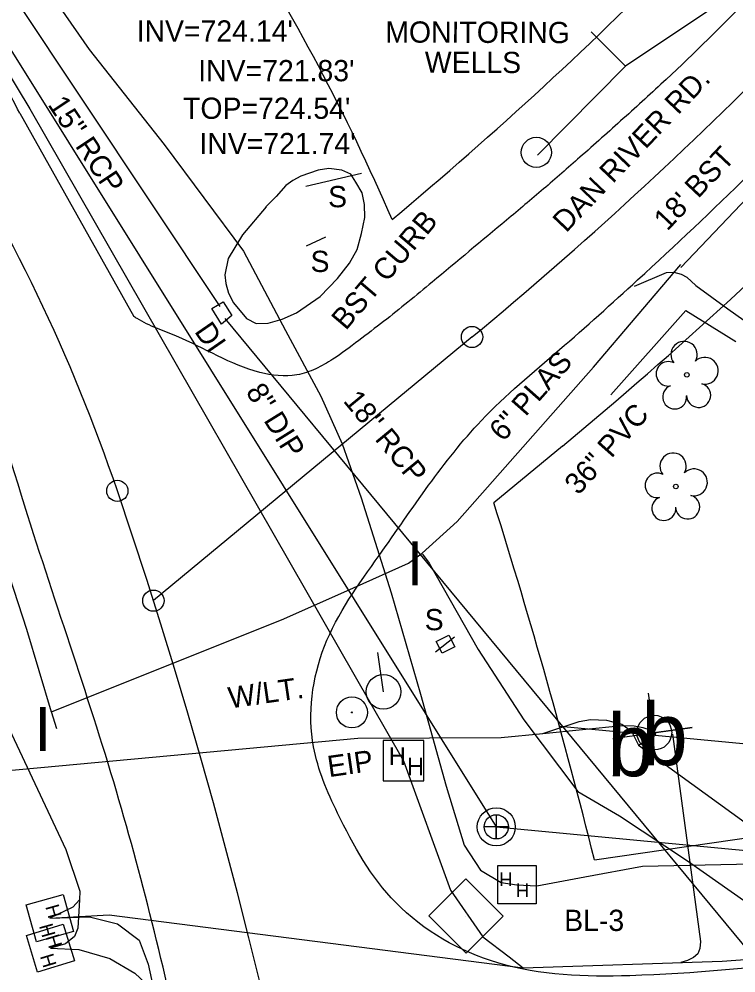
# Model space of a CAD drawing. Extents: x 1645945 to 2447332, y 713118 to 970361.
# Drawn here: x 1646260.5 to 1646361.8, y 969454.4 to 969589.2 of the extents above; entities that cross this region are included whole.
import ezdxf

# ---------------------------------------------------------------- set-up
doc = ezdxf.new("R2010")
doc.units = 0
for name, color, linetype in [('CTL Secondary Horizontal and Vertical CELL', 7, 'Continuous'), ('CTL Secondary Horizontal and Vertical Text', 7, 'Continuous'), ('Exist Horizontal Alignment', 7, 'Continuous'), ('Exist Horizontal Alignment Station Label', 7, 'Continuous'), ('Exist Other Culture Area Outline', 7, 'Continuous'), ('Exist Other Culture Area Outline Text', 7, 'Continuous'), ('Exist Other Culture Fence Line', 7, 'Continuous'), ('Exist Other Culture Fence Line Text', 7, 'Continuous'), ('Exist Other Culture Sign CELL', 7, 'Continuous'), ('Exist Other Culture Well CELL', 7, 'Continuous'), ('Exist Other Culture Well Leader', 7, 'Continuous'), ('Exist Other Culture Well Text', 7, 'Continuous'), ('Exist Property Iron Pin CELL', 7, 'Continuous'), ('Exist Property Iron Pin Text', 7, 'Continuous'), ('Exist Right of Way Easement Line', 7, 'Continuous'), ('Exist Right of Way Line', 7, 'Continuous'), ('Exist Roads Curbs', 7, 'Continuous'), ('Exist Roads Curbs Text', 7, 'Continuous'), ('Exist Roads EOP', 7, 'Continuous'), ('Exist Roads EOP Text', 7, 'Continuous'), ('Exist Roads Soil', 7, 'Continuous'), ('Exist Structure Minor Drop Inlet', 7, 'Continuous'), ('Exist Structure Minor Drop Inlet Text', 7, 'Continuous'), ('Exist Structure Minor Drop Inlet Top Elevation', 7, 'Continuous'), ('Exist Structure Minor Pipes RCP 15 Inch', 7, 'Continuous'), ('Exist Structure Minor Pipes RCP 15 Inch Invert', 7, 'Continuous'), ('Exist Structure Minor Pipes RCP 15 Inch Text', 7, 'Continuous'), ('Exist Structure Minor Pipes RCP 18 Inch', 7, 'Continuous'), ('Exist Structure Minor Pipes RCP 18 Inch Text', 7, 'Continuous'), ('Exist Utilities Power Joint Use Telephone CELL', 7, 'Continuous'), ('Exist Utilities Power Pole CELL', 7, 'Continuous'), ('Exist Utilities Power Pole Text', 7, 'Continuous'), ('Exist Utilities Sanitary Sewer Manhole CELL', 7, 'Continuous'), ('Exist Utilities Sanitary Sewer UG Line', 7, 'Continuous'), ('Exist Utilities Sanitary Sewer UG Line Text', 7, 'Continuous'), ('Exist Utilities Telephone Hand Hole CELL', 7, 'Continuous'), ('Exist Utilities Telephone Pedestal CELL', 7, 'Continuous'), ('Exist Utilities Telephone UG Cable SUE LOS C', 7, 'Continuous'), ('Exist Utilities Telephone UG Conduit SUE LOS B', 7, 'Continuous'), ('Exist Utilities Telephone UG FO SUE LOS C', 7, 'Continuous'), ('Exist Utilities Water UG Line SUE LOS B', 7, 'Continuous'), ('Exist Utilities Water UG Line SUE LOS B Text', 7, 'Continuous'), ('Exist Utilities Water UG Line SUE LOS C', 7, 'Continuous'), ('Exist Utilities Water Valve CELL', 7, 'Continuous'), ('Exist Vegetation Tree CELL', 7, 'Continuous')]:
    doc.layers.add(name, color=color, linetype=linetype)

msp = doc.modelspace()

# ---------------------------------------------------------------- linework, layer by layer
at = {"layer": 'CTL Secondary Horizontal and Vertical CELL'}
msp.add_line((1646323.61, 969462.44), (1646323.61, 969462.44), dxfattribs=at)
msp.add_lwpolyline([(1646318.4, 969462.45), (1646323.64, 969467.69), (1646328.89, 969462.44), (1646323.65, 969457.2)], close=True, dxfattribs=at)
at = {"layer": 'Exist Horizontal Alignment'}
msp.add_line((1646324.5, 969544.25), (1646279.5, 969507), dxfattribs=at)
for centre, radius, start, end in [((1645951.5, 969994.91), 585, 309.61403, 315.58305), ((1646037.69, 969442.13), 250, 18.755, 32.506), ((1645516.89, 969265.29), 800, 348.6692, 18.755)]:
    msp.add_arc(centre, radius, start, end, dxfattribs=at)
at = {"layer": 'Exist Horizontal Alignment Station Label'}
for centre in [(1646324.5, 969544.25), (1646274.41, 969522.51), (1646279.5, 969507)]:
    msp.add_circle(centre, 1.5, dxfattribs=at)
at = {"layer": 'Exist Other Culture Area Outline'}
msp.add_line((1646319.33, 969499.79), (1646322.04, 969501.87), dxfattribs=at)
msp.add_lwpolyline([(1646320.26, 969499.57), (1646319.42, 969501.22), (1646321.21, 969502.13), (1646322.05, 969500.47)], close=True, dxfattribs=at)
at = {"layer": 'Exist Other Culture Fence Line'}
msp.add_lwpolyline([(1646344.12, 969536.08), (1646354.69, 969547.97), (1646361.73, 969543.63)], dxfattribs=at)
at = {"layer": 'Exist Other Culture Sign CELL'}
for p, q in [((1646308.88, 969567.37), (1646301.02, 969565.53)), ((1646303.79, 969558.36), (1646301.06, 969557.1))]:
    msp.add_line(p, q, dxfattribs=at)
at = {"layer": 'Exist Other Culture Well CELL'}
msp.add_circle((1646333.58, 969570.33), 2.13, dxfattribs=at)
at = {"layer": 'Exist Other Culture Well Leader'}
msp.add_line((1646333.76, 969569.92), (1646346.18, 969582.49), dxfattribs=at)
msp.add_lwpolyline([(1646359.5, 969591.41), (1646346.18, 969582.49), (1646341.32, 969587.35)], dxfattribs=at)
at = {"layer": 'Exist Property Iron Pin CELL'}
for radius in [2.2, 0.0707]:
    msp.add_circle((1646307.54, 969491.21), radius, dxfattribs=at)
at = {"layer": 'Exist Right of Way Easement Line'}
msp.add_lwpolyline([(1646336.92, 969489.25), (1646418.86, 969481.48)], dxfattribs=at)
at = {"layer": 'Exist Right of Way Line'}
for p, q in [((1646341.77, 969470.4), (1647145.86, 969586)), ((1646337.25, 969528.84), (1646327.57, 969520.83))]:
    msp.add_line(p, q, dxfattribs=at)
for centre, radius, start, end in [((1646037.69, 969442.13), 300, 23.3127, 32.506), ((1645951.5, 969994.91), 565, 309.8047, 315.5831), ((1645951.5, 969994.91), 605, 309.61403, 315.58305), ((1645516.89, 969265.29), 850, 13.9633, 17.49529)]:
    msp.add_arc(centre, radius, start, end, dxfattribs=at)
at = {"layer": 'Exist Roads Curbs'}
msp.add_lwpolyline([(1646295.43, 969562.64), (1646292.06, 969558.68), (1646290.06, 969555.35), (1646289.58, 969553.03), (1646289.73, 969551.79), (1646290.09, 969550.42), (1646290.82, 969549.09), (1646292.67, 969546.84), (1646294.03, 969546.16), (1646295.71, 969546.19), (1646297.68, 969546.75), (1646299.72, 969547.66), (1646303.07, 969549.98), (1646305.48, 969552.5), (1646307.21, 969554.66), (1646308.27, 969556.62), (1646308.89, 969558.87), (1646309.36, 969561.15), (1646309.33, 969562.99), (1646308.98, 969564.6), (1646308.11, 969566.11), (1646307.37, 969567.25), (1646306.11, 969567.84), (1646304.27, 969568.05), (1646302.79, 969567.83), (1646300.34, 969566.95), (1646299.19, 969566.37), (1646298.18, 969565.67), (1646296.86, 969564.09), (1646295.4, 969562.62)], dxfattribs=at)
at = {"layer": 'Exist Roads EOP'}
msp.add_line((1646260.63, 969575.85), (1646276.76, 969547.14), dxfattribs=at)
for points in [[(1646260.63, 969575.85), (1646258.14, 969580.63), (1646251.55, 969591.51), (1646244.97, 969602.4), (1646238.35, 969613.26), (1646231.63, 969624.06), (1646202.27, 969670.52)], [(1646384.59, 969614.07), (1646363.63, 969592.14), (1646351.92, 969580.65), (1646345.86, 969575.11), (1646339.73, 969569.64), (1646334.58, 969565.16), (1646329.36, 969560.75), (1646318.86, 969552), (1646315.45, 969549.18), (1646312.01, 969546.44), (1646308.49, 969543.75), (1646304.83, 969541.11), (1646302.42, 969539.76), (1646299.77, 969538.9), (1646294.52, 969539.25), (1646282.77, 969544.37), (1646279.95, 969545.5), (1646277.2, 969546.85), (1646276.76, 969547.14)], [(1646373.7, 969456.15), (1646346.78, 969454.01), (1646328.12, 969455.82), (1646313.73, 969464.34), (1646305.52, 969476.97), (1646302.12, 969486.35), (1646303.66, 969500.55), (1646311.37, 969513.37), (1646318.37, 969523.3), (1646325.82, 969532.44), (1646336.85, 969542.47), (1646347.88, 969552.31), (1646363.63, 969567.2), (1646396.16, 969600.3)], [(1646287.33, 969128.01), (1646293.09, 969167.33), (1646297.37, 969211.3), (1646298.43, 969249.08), (1646298.55, 969271.82), (1646297.44, 969288.13), (1646293.89, 969300.95), (1646296.41, 969302.95), (1646298.17, 969306.12), (1646298.27, 969332.13), (1646295.51, 969374.21), (1646289.77, 969414.06), (1646284.35, 969440.07), (1646274.28, 969480.08), (1646260.88, 969521.84), (1646237.07, 969568.06), (1646226.33, 969574.21), (1646210.08, 969580.6)]]:
    msp.add_spline(points, degree=3, dxfattribs=at)
at = {"layer": 'Exist Roads Soil'}
msp.add_lwpolyline([(1646347.43, 969551.41), (1646351.96, 969553.34), (1646352.99, 969553.42), (1646354.05, 969553.13), (1646354.84, 969552.71), (1646356.12, 969551.54), (1646360.63, 969548.24), (1646366.62, 969543.99)], dxfattribs=at)
at = {"layer": 'Exist Structure Minor Drop Inlet'}
msp.add_lwpolyline([(1646289.34, 969549.21), (1646290.58, 969547.29), (1646289.12, 969546.04), (1646287.76, 969548.29), (1646289.34, 969549.21)], dxfattribs=at)
at = {"layer": 'Exist Structure Minor Pipes RCP 15 Inch'}
msp.add_line((1646258.04, 969594.97), (1646288.86, 969548.56), dxfattribs=at)
at = {"layer": 'Exist Structure Minor Pipes RCP 18 Inch'}
msp.add_line((1646289.57, 969546.84), (1646404.84, 969407.5), dxfattribs=at)
at = {"layer": 'Exist Utilities Power Joint Use Telephone CELL'}
msp.add_line((1646350.24, 969488.34), (1646350.24, 969488.34), dxfattribs=at)
msp.add_lwpolyline([(1646344.36, 969487.51), (1646355.59, 969489.07), (1646350.24, 969488.32), (1646349.44, 969493.91)], dxfattribs=at)
msp.add_circle((1646350.24, 969488.35), 2.45, dxfattribs=at)
at = {"layer": 'Exist Utilities Power Pole CELL'}
for q in [(1646311.21, 969499.69), (1646311.98, 969494.12)]:
    msp.add_line((1646311.98, 969494.12), q, dxfattribs=at)
msp.add_circle((1646311.98, 969494.12), 2.45, dxfattribs=at)
at = {"layer": 'Exist Utilities Sanitary Sewer Manhole CELL'}
msp.add_lwpolyline([(1646327.92, 969476.75), (1646327.92, 969473.33), (1646327.92, 969475.04), (1646329.63, 969475.04), (1646326.2, 969475.04)], dxfattribs=at)
for radius in [2.69, 1.71]:
    msp.add_circle((1646327.92, 969475.04), radius, dxfattribs=at)
at = {"layer": 'Exist Utilities Sanitary Sewer UG Line'}
msp.add_line((1646096.45, 969845.65), (1646327.92, 969475.04), dxfattribs=at)
msp.add_lwpolyline([(1646327.92, 969475.04), (1646424.85, 969465.85), (1646580.36, 969512.56)], dxfattribs=at)
at = {"layer": 'Exist Utilities Telephone Hand Hole CELL'}
for p, q in [((1646311.95, 969487.24), (1646311.95, 969481.52)), ((1646317.67, 969487.24), (1646311.95, 969487.24)), ((1646317.67, 969481.52), (1646317.67, 969487.24)), ((1646314.81, 969484.38), (1646314.81, 969484.38)), ((1646311.95, 969481.52), (1646317.67, 969481.52))]:
    msp.add_line(p, q, dxfattribs=at)
for points in [[(1646328.12, 969469.58), (1646333.55, 969469.58), (1646333.55, 969464.15), (1646328.12, 969464.15)], [(1646262.97, 969458.81), (1646261.52, 969464.03), (1646266.74, 969465.49), (1646268.2, 969460.26)], [(1646263.15, 969454.51), (1646261.57, 969459.7), (1646266.76, 969461.28), (1646268.34, 969456.09)]]:
    msp.add_lwpolyline(points, close=True, dxfattribs=at)
at = {"layer": 'Exist Utilities Telephone UG Cable SUE LOS C'}
msp.add_line((1646348.02, 969486.6), (1646350.45, 969488.12), dxfattribs=at)
for points in [[(1646348.02, 969486.6), (1646366.85, 969472.94), (1646377.35, 969466.91), (1646386.89, 969463.79), (1646398.95, 969462.04), (1646412.76, 969463.41), (1646611.06, 969492.42), (1646611.12, 969496.71)], [(1646334.49, 969488.23), (1646339.61, 969489.93), (1646341.21, 969490.22), (1646343.49, 969490.11), (1646345.64, 969489.53), (1646347.02, 969488.55), (1646348.02, 969486.6)]]:
    msp.add_lwpolyline(points, dxfattribs=at)
at = {"layer": 'Exist Utilities Telephone UG Conduit SUE LOS B'}
msp.add_lwpolyline([(1646261.48, 969597.75), (1646270.44, 969584.88), (1646281.01, 969571.46), (1646292.24, 969556.38), (1646298.14, 969545.17), (1646303.16, 969535.88), (1646306.14, 969529.17), (1646308.84, 969521.51), (1646313.09, 969508.09), (1646317.22, 969493.8), (1646320.85, 969480.79), (1646323.39, 969472.46), (1646325.68, 969468.92), (1646328.62, 969467.19), (1646330.84, 969466.86), (1646333.65, 969466.71), (1646340.42, 969467.97), (1646348.59, 969469.48), (1646364.06, 969469.8)], dxfattribs=at)
at = {"layer": 'Exist Utilities Telephone UG FO SUE LOS C'}
for points in [[(1646202.85, 969671.1), (1646244.91, 969604.9), (1646262.03, 969576.49), (1646314.81, 969484.38), (1646321.44, 969466.08), (1646326, 969459.52), (1646329.74, 969456.67), (1646331.74, 969455.12)], [(1646203.85, 969604.15), (1646211.74, 969590.22), (1646241.23, 969526.88), (1646267.12, 969471.85), (1646269.09, 969465.94)], [(1646264.86, 969462.15), (1646273.24, 969462.6), (1646331.74, 969455.12), (1646359.82, 969456.07), (1646401.7, 969459.13), (1646565.45, 969482.97), (1646568.22, 969483.91), (1646570.89, 969486.36), (1646573.89, 969488.03), (1646577, 969489.47), (1646583.56, 969490.7), (1646611.12, 969496.71)], [(1646222.72, 969495.57), (1646224.3, 969493.47), (1646226.73, 969491.26), (1646234, 969487.45), (1646241.22, 969485.34), (1646258.01, 969482.89), (1646308.38, 969487.57), (1646328.61, 969487.68), (1646334.49, 969488.23)], [(1646334.49, 969488.23), (1646345.71, 969489.34), (1646347.37, 969489.29), (1646348.62, 969489.1), (1646349.67, 969488.73), (1646350.45, 969488.12)], [(1646352.82, 969488.15), (1646356.78, 969458.83), (1646356.69, 969457.85), (1646356.4, 969457.1), (1646355.78, 969456.56), (1646354.93, 969456.15), (1646353.98, 969455.87)], [(1646269.09, 969465.94), (1646269.05, 969464.74), (1646268.11, 969463.68), (1646264.86, 969462.15)], [(1646269.05, 969464.74), (1646268.82, 969460.74), (1646268.35, 969459.56), (1646267.1, 969458.53), (1646264.95, 969457.89)], [(1646264.86, 969462.15), (1646270.48, 969462.33), (1646274.42, 969461.34), (1646277.49, 969459.04), (1646278.74, 969455.63), (1646279.95, 969450.23)], [(1646264.95, 969457.89), (1646268.95, 969457.73), (1646273.33, 969456.42), (1646276.89, 969454.35), (1646279.14, 969452.23), (1646279.95, 969450.23), (1646280.35, 969448.45)]]:
    msp.add_lwpolyline(points, dxfattribs=at)
at = {"layer": 'Exist Utilities Water UG Line SUE LOS B'}
for points in [[(1646353.96, 969554.05), (1646376.58, 969577.81), (1646398.98, 969599.72), (1646421.44, 969623.58), (1646430.02, 969632.82), (1646453.53, 969657.83), (1646482.44, 969687.58), (1646504.67, 969710.19), (1646505.36, 969709.45), (1646509.94, 969704.89)], [(1646170.24, 969666.26), (1646179.89, 969651.43), (1646195.41, 969627.85), (1646201.47, 969617.31), (1646211.97, 969599.71), (1646220.72, 969587.04), (1646228.76, 969575.31), (1646233.7, 969567.15), (1646240.29, 969555.33), (1646247.6, 969540.83), (1646253.09, 969528.92), (1646261.6, 969502.98), (1646265.06, 969491.29)], [(1646265.86, 969488.87), (1646265.11, 969491.29), (1646297.92, 969504.44), (1646307.78, 969508.81), (1646315.53, 969512.29), (1646317.46, 969513.71), (1646322.38, 969518.18), (1646341.65, 969539.99), (1646353.99, 969554.49)], [(1646317.5, 969513.57), (1646318.42, 969512.28), (1646325.38, 969500.08), (1646331.82, 969490.15), (1646339.42, 969480.04), (1646345.34, 969476.59), (1646354.93, 969470.25)]]:
    msp.add_lwpolyline(points, dxfattribs=at)
at = {"layer": 'Exist Utilities Water UG Line SUE LOS C'}
msp.add_lwpolyline([(1646354.93, 969470.25), (1646371.68, 969458.45), (1646376.94, 969427.38), (1646526.58, 969451.43), (1646539.94, 969453.64), (1646540.7, 969449.56)], dxfattribs=at)
at = {"layer": 'Exist Vegetation Tree CELL'}
for p, q in [((1646354.83, 969538.9), (1646354.83, 969538.9)), ((1646353.28, 969523.13), (1646353.28, 969523.13))]:
    msp.add_line(p, q, dxfattribs=at)
for centre in [(1646354.83, 969538.9), (1646353.28, 969523.13)]:
    msp.add_circle(centre, 0.326, dxfattribs=at)
for centre, radius, start, end in [((1646354.44, 969541.77), 1.86, 330.1651, 219.7134), ((1646352.22, 969539.05), 1.73, 62.6636, 279.3457), ((1646357.37, 969539.48), 1.9, 257.1011, 134.1999), ((1646356.5, 969536), 1.7, 181.2822, 74.56), ((1646353.12, 969535.77), 1.69, 111.5671, 6.231), ((1646352.89, 969526), 1.86, 330.1651, 219.7134), ((1646355.83, 969523.71), 1.9, 257.1011, 134.1999), ((1646350.67, 969523.28), 1.73, 62.6636, 279.3457), ((1646351.58, 969520.01), 1.69, 111.5671, 6.231), ((1646354.95, 969520.23), 1.7, 181.2822, 74.56)]:
    msp.add_arc(centre, radius, start, end, dxfattribs=at)

# ---------------------------------------------------------------- texts
at = {"layer": 'CTL Secondary Horizontal and Vertical Text'}
msp.add_text('BL-3', height=3, dxfattribs=at).set_placement((1646337.51, 969460.33))
at = {"layer": 'Exist Other Culture Area Outline Text'}
for p in [(1646304.17, 969562.58), (1646301.69, 969553.43), (1646317.81, 969502.82)]:
    msp.add_text('S', height=3, dxfattribs=at).set_placement(p)
at = {"layer": 'Exist Other Culture Fence Line Text'}
msp.add_text('36" PVC', height=3, rotation=48.3766, dxfattribs=at).set_placement((1646339.53, 969521.79))
at = {"layer": 'Exist Other Culture Well Text'}
for s, p in [('MONITORING', (1646312.24, 969585.85)), ('WELLS', (1646317.82, 969581.58))]:
    msp.add_text(s, height=3, rotation=359.797, dxfattribs=at).set_placement(p)
at = {"layer": 'Exist Property Iron Pin Text'}
msp.add_text('EIP', height=3, rotation=8.1684, dxfattribs=at).set_placement((1646304.3, 969482.05))
at = {"layer": 'Exist Roads Curbs Text'}
msp.add_text('BST CURB', height=3, rotation=49.6135, dxfattribs=at).set_placement((1646306.67, 969545.07))
at = {"layer": 'Exist Roads EOP Text'}
for s, rotation, p in [('DAN RIVER RD.', 46.4583, (1646337.78, 969558.88)), ("18' BST", 46.5771, (1646352.06, 969559.11))]:
    msp.add_text(s, height=3, rotation=rotation, dxfattribs=at).set_placement(p)
at = {"layer": 'Exist Structure Minor Drop Inlet Text'}
msp.add_text('DI', height=3, rotation=304.6263, dxfattribs=at).set_placement((1646285.2, 969545.03))
at = {"layer": 'Exist Structure Minor Drop Inlet Top Elevation'}
msp.add_text("TOP=724.54'", height=3, dxfattribs=at).set_placement((1646283.69, 969575.07))
at = {"layer": 'Exist Structure Minor Pipes RCP 15 Inch Invert'}
for s, p in [("INV=724.14'", (1646277.13, 969585.98)), ("INV=721.83'", (1646285.83, 969580.38)), ("INV=721.74'", (1646285.99, 969570.08))]:
    msp.add_text(s, height=3, dxfattribs=at).set_placement(p)
at = {"layer": 'Exist Structure Minor Pipes RCP 15 Inch Text'}
msp.add_text('15" RCP', height=3, rotation=303.5865, dxfattribs=at).set_placement((1646264.5, 969577.08))
at = {"layer": 'Exist Structure Minor Pipes RCP 18 Inch Text'}
msp.add_text('18" RCP', height=3, rotation=309.598, dxfattribs=at).set_placement((1646306.2, 969535.18))
at = {"layer": 'Exist Utilities Power Pole Text'}
msp.add_text('W/LT.', height=3, rotation=8.1684, dxfattribs=at).set_placement((1646290.3, 969491.76))
at = {"layer": 'Exist Utilities Sanitary Sewer UG Line Text'}
msp.add_text('8" DIP', height=3, rotation=301.9876, dxfattribs=at).set_placement((1646292.46, 969536.53))
at = {"layer": 'Exist Utilities Telephone Hand Hole CELL'}
for p in [(1646312.73, 969483.79), (1646315.3, 969482.32)]:
    msp.add_text('H', height=2.5, dxfattribs=at).set_placement(p)
for rotation, p in [(180, (1646330.2, 969468.62)), (180, (1646332.57, 969467.06)), (285.5782, (1646264.21, 969463.77)), (285.5782, (1646263.34, 969461.06)), (286.9414, (1646264.26, 969459.5)), (286.9414, (1646263.46, 969456.77))]:
    msp.add_text('H', height=1.94, rotation=rotation, dxfattribs=at).set_placement(p)
at = {"layer": 'Exist Utilities Telephone Pedestal CELL'}
for p in [(1646348.41, 969483.75), (1646343.61, 969482.19)]:
    msp.add_text('b', height=8.81, dxfattribs=at).set_placement(p)
at = {"layer": 'Exist Utilities Water UG Line SUE LOS B Text'}
msp.add_text('6" PLAS', height=3, rotation=48.5211, dxfattribs=at).set_placement((1646328.9, 969529.34))
at = {"layer": 'Exist Utilities Water Valve CELL'}
for p in [(1646315.29, 969509.15), (1646262.73, 969485.74)]:
    msp.add_text('I', height=6.25, dxfattribs=at).set_placement(p)

doc.saveas('drawing.dxf')
